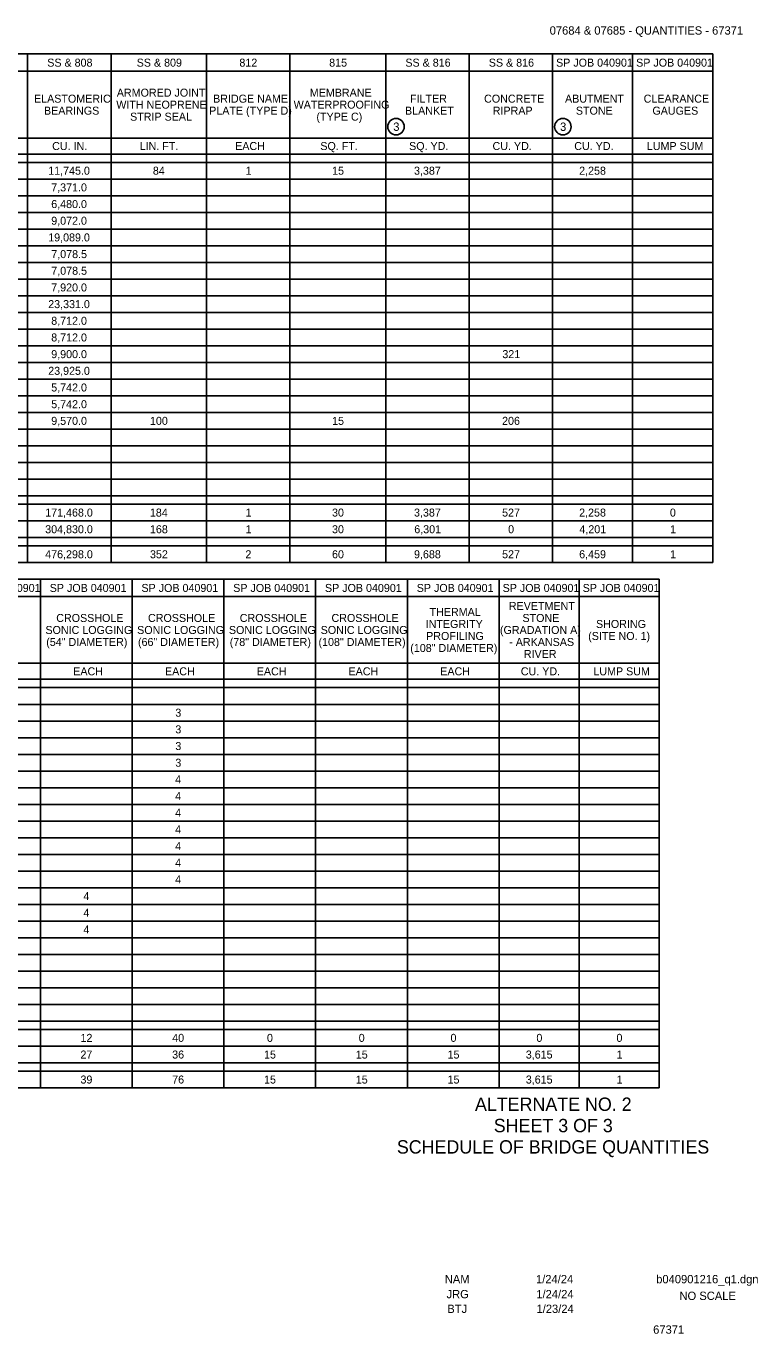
# Model space of a CAD drawing. Extents: x 0.06 to 1.36, y 0.04 to 0.85.
# Drawn here: x 0.905 to 1.362, y 0.037 to 0.854 of the extents above; entities that cross this region are included whole.
import ezdxf

# ---------------------------------------------------------------- set-up
doc = ezdxf.new("R2010")
doc.units = 0
for name, color, linetype in [('R_Shade By Others', 7, 'Continuous'), ('R_Survey Control', 7, 'Continuous'), ('R_Wall', 7, 'Continuous')]:
    doc.layers.add(name, color=color, linetype=linetype)

msp = doc.modelspace()

# ---------------------------------------------------------------- linework, layer by layer
at = {"layer": 'R_Survey Control'}
for p, q in [((0.07508, 0.83695), (1.33392, 0.83695)), ((0.90615, 0.83695), (0.90615, 0.51924)), ((0.95823, 0.83695), (0.95823, 0.51924)), ((1.0178, 0.83695), (1.0178, 0.51924)), ((1.06988, 0.83695), (1.06988, 0.51924)), ((1.12978, 0.83695), (1.12978, 0.51924)), ((1.18186, 0.83695), (1.18186, 0.51924)), ((1.23394, 0.83695), (1.23394, 0.51924)), ((1.28392, 0.83695), (1.28392, 0.51924)), ((1.33392, 0.83695), (1.33392, 0.51924)), ((0.2593, 0.78445), (1.33392, 0.78445)), ((0.07508, 0.77445), (1.33392, 0.77445)), ((0.11154, 0.76924), (1.33392, 0.76924)), ((0.11154, 0.75883), (1.33392, 0.75883)), ((0.11154, 0.74841), (1.33392, 0.74841)), ((0.11154, 0.73799), (1.33392, 0.73799)), ((0.11154, 0.72758), (1.33392, 0.72758)), ((0.11154, 0.71716), (1.33392, 0.71716)), ((0.11154, 0.70674), (1.33392, 0.70674)), ((0.11154, 0.69633), (1.33392, 0.69633)), ((0.11154, 0.68591), (1.33392, 0.68591)), ((0.11154, 0.67549), (1.33392, 0.67549)), ((0.11154, 0.66508), (1.33392, 0.66508)), ((0.11154, 0.65466), (1.33392, 0.65466)), ((0.11154, 0.64424), (1.33392, 0.64424)), ((0.11154, 0.63383), (1.33392, 0.63383)), ((0.11154, 0.62341), (1.33392, 0.62341)), ((0.11154, 0.61299), (1.33392, 0.61299)), ((0.11154, 0.60258), (1.33392, 0.60258)), ((0.11154, 0.59216), (1.33392, 0.59216)), ((0.11154, 0.58174), (1.33392, 0.58174)), ((0.11154, 0.57133), (1.33392, 0.57133)), ((0.07508, 0.5557), (1.33392, 0.5557)), ((0.11154, 0.56091), (1.33392, 0.56091)), ((0.07508, 0.54529), (1.33392, 0.54529)), ((0.07508, 0.53487), (1.33392, 0.53487)), ((0.07508, 0.52966), (1.33392, 0.52966)), ((0.07508, 0.51924), (1.33392, 0.51924)), ((0.07508, 0.50883), (1.30054, 0.50883)), ((0.9141, 0.50883), (0.9141, 0.19112)), ((0.97139, 0.50883), (0.97139, 0.19112)), ((1.02868, 0.50883), (1.02868, 0.19112)), ((1.08598, 0.50883), (1.08598, 0.19112)), ((1.14327, 0.50883), (1.14327, 0.19112)), ((1.20056, 0.50883), (1.20056, 0.19112)), ((1.25055, 0.50883), (1.25055, 0.19112)), ((1.30054, 0.50883), (1.30054, 0.19112)), ((0.2593, 0.45633), (1.30054, 0.45633)), ((0.07508, 0.44633), (1.30054, 0.44633)), ((0.11154, 0.44112), (1.30054, 0.44112)), ((0.11154, 0.4307), (1.30054, 0.4307)), ((0.11154, 0.42029), (1.30054, 0.42029)), ((0.11154, 0.40987), (1.30054, 0.40987)), ((0.11154, 0.39945), (1.30054, 0.39945)), ((0.11154, 0.38904), (1.30054, 0.38904)), ((0.11154, 0.37862), (1.30054, 0.37862)), ((0.11154, 0.3682), (1.30054, 0.3682)), ((0.11154, 0.35779), (1.30054, 0.35779)), ((0.11154, 0.34737), (1.30054, 0.34737)), ((0.11154, 0.33695), (1.30054, 0.33695)), ((0.11154, 0.32654), (1.30054, 0.32654)), ((0.11154, 0.31612), (1.30054, 0.31612)), ((0.11154, 0.3057), (1.30054, 0.3057)), ((0.11154, 0.29529), (1.30054, 0.29529)), ((0.11154, 0.28487), (1.30054, 0.28487)), ((0.11154, 0.27445), (1.30054, 0.27445)), ((0.11154, 0.26404), (1.30054, 0.26404)), ((0.11154, 0.25362), (1.30054, 0.25362)), ((0.11154, 0.2432), (1.30054, 0.2432)), ((0.11154, 0.23279), (1.30054, 0.23279)), ((0.07508, 0.22758), (1.30054, 0.22758)), ((0.07508, 0.21716), (1.30054, 0.21716)), ((0.07508, 0.20674), (1.30054, 0.20674)), ((0.07508, 0.20154), (1.30054, 0.20154)), ((0.07508, 0.19112), (1.30054, 0.19112))]:
    msp.add_line(p, q, dxfattribs=at)
for points in [[(0.2593, 0.82612), (0.30425, 0.82612), (0.41883, 0.82612), (0.46733, 0.82612), (0.509, 0.82612), (0.55587, 0.82612), (0.59233, 0.82612), (0.6366, 0.82612), (0.68087, 0.82612), (0.74858, 0.82612), (0.79433, 0.82612), (0.84642, 0.82612), (0.94537, 0.82612), (1.00267, 0.82612), (1.06517, 0.82612), (1.19277, 0.82612), (1.26048, 0.82612), (1.31256, 0.82612), (1.33392, 0.82612)], [(0.2593, 0.49799), (0.30425, 0.49799), (0.36154, 0.49799), (0.40321, 0.49799), (0.44487, 0.49799), (0.49175, 0.49799), (0.52821, 0.49799), (0.58029, 0.49799), (0.64019, 0.49799), (0.7079, 0.49799), (0.75998, 0.49799), (0.81206, 0.49799), (0.85894, 0.49799), (0.86623, 0.49799), (0.92873, 0.49799), (0.99644, 0.49799), (1.06415, 0.49799), (1.11623, 0.49799), (1.16831, 0.49799), (1.30054, 0.49799)]]:
    msp.add_lwpolyline(points, dxfattribs=at)
at = {"layer": 'R_Wall'}
for centre in [(1.13618, 0.79152), (1.24035, 0.79152)]:
    msp.add_circle(centre, 0.00515, dxfattribs=at)

# ---------------------------------------------------------------- texts
at = {"layer": 'R_Shade By Others'}
for s, height, p in [('07684 & 07685 - QUANTITIES - 67371', 0.0052083, (1.23211, 0.84904)), ('ALTERNATE NO. 2', 0.0083332, (1.18545, 0.17677)), ('SHEET 3 OF 3', 0.0083332, (1.1972, 0.16344)), ('SCHEDULE OF BRIDGE QUANTITIES', 0.0083332, (1.13669, 0.1501)), ('NAM', 0.005208, (1.1666, 0.06906)), ('1/24/24', 0.005208, (1.22357, 0.06906)), ('b040901216_q1.dgn', 0.0052083, (1.29862, 0.06906)), ('JRG', 0.005208, (1.1677, 0.05969)), ('1/24/24', 0.005208, (1.22378, 0.05969)), ('NO SCALE', 0.005208, (1.31316, 0.05864)), ('BTJ', 0.005208, (1.16819, 0.05052)), ('1/23/24', 0.005208, (1.22389, 0.05052)), ('67371', 0.005208, (1.29672, 0.03756))]:
    msp.add_text(s, height=height, dxfattribs=at).set_placement(p)
at = {"layer": 'R_Survey Control'}
for s, p in [('SS & 808', (0.91839, 0.82904)), ('SS & 809', (0.97424, 0.82904)), ('812', (1.03836, 0.82904)), ('815', (1.09443, 0.82904)), ('SS & 816', (1.14201, 0.82904)), ('SS & 816', (1.19409, 0.82904)), ('SP JOB 040901', (1.2361, 0.82904)), ('SP JOB 040901', (1.2861, 0.82904)), ('ELASTOMERIC', (0.91013, 0.80654)), ('ARMORED JOINT', (0.96182, 0.81029)), ('BRIDGE NAME', (1.02194, 0.80654)), ('MEMBRANE', (1.08232, 0.81029)), ('FILTER', (1.14491, 0.80654)), ('CONCRETE', (1.19116, 0.80654)), ('ABUTMENT', (1.24169, 0.80654)), ('CLEARANCE', (1.29079, 0.80654)), ('BEARINGS', (0.91634, 0.79904)), ('WITH NEOPRENE', (0.9615, 0.80279)), ('PLATE (TYPE D)', (1.01949, 0.79904)), ('WATERPROOFING', (1.07225, 0.80279)), ('(TYPE C)', (1.08648, 0.79529)), ('BLANKET', (1.14177, 0.79904)), ('RIPRAP', (1.19656, 0.79904)), ('STONE', (1.24846, 0.79904)), ('GAUGES', (1.29626, 0.79904)), ('STRIP SEAL', (0.9701, 0.79529)), ('CU. IN.', (0.92146, 0.77695)), ('LIN. FT.', (0.97609, 0.77695)), ('EACH', (1.03572, 0.77695)), ('SQ. FT.', (1.0889, 0.77695)), ('SQ. YD.', (1.14432, 0.77695)), ('CU. YD.', (1.19643, 0.77695)), ('CU. YD.', (1.24746, 0.77695)), ('LUMP SUM', (1.29277, 0.77695)), ('11,745.0', (0.91899, 0.76154)), ('84', (0.98435, 0.76154)), ('1', (1.04224, 0.76154)), ('15', (1.09625, 0.76154)), ('3,387', (1.1474, 0.76154)), ('2,258', (1.25051, 0.76154)), ('7,371.0', (0.92087, 0.75112)), ('6,480.0', (0.92087, 0.7407)), ('9,072.0', (0.92087, 0.73029)), ('19,089.0', (0.91899, 0.71987)), ('7,078.5', (0.92091, 0.70945)), ('7,078.5', (0.92091, 0.69904)), ('7,920.0', (0.92087, 0.68862)), ('23,331.0', (0.91899, 0.6782)), ('8,712.0', (0.92087, 0.66779)), ('8,712.0', (0.92087, 0.65737)), ('9,900.0', (0.92087, 0.64695)), ('321', (1.20255, 0.64695)), ('23,925.0', (0.91899, 0.63654)), ('5,742.0', (0.92087, 0.62612)), ('5,742.0', (0.92087, 0.6157)), ('9,570.0', (0.92087, 0.60529)), ('100', (0.98253, 0.60529)), ('15', (1.09625, 0.60529)), ('206', (1.20239, 0.60529)), ('171,468.0', (0.91711, 0.54799)), ('184', (0.98247, 0.54799)), ('1', (1.04224, 0.54799)), ('30', (1.09621, 0.54799)), ('3,387', (1.1474, 0.54799)), ('527', (1.2024, 0.54799)), ('2,258', (1.25051, 0.54799)), ('0', (1.30718, 0.54799)), ('304,830.0', (0.91711, 0.53758)), ('168', (0.98251, 0.53758)), ('1', (1.04224, 0.53758)), ('30', (1.09621, 0.53758)), ('6,301', (1.14755, 0.53758)), ('0', (1.20616, 0.53758)), ('4,201', (1.25066, 0.53758)), ('1', (1.30732, 0.53758)), ('476,298.0', (0.91711, 0.52195)), ('352', (0.98254, 0.52195)), ('2', (1.04212, 0.52195)), ('60', (1.09621, 0.52195)), ('9,688', (1.1474, 0.52195)), ('527', (1.2024, 0.52195)), ('6,459', (1.25053, 0.52195)), ('1', (1.30732, 0.52195)), ('SP JOB 040901', (0.86628, 0.50091)), ('SP JOB 040901', (0.91992, 0.50091)), ('SP JOB 040901', (0.97721, 0.50091)), ('SP JOB 040901', (1.0345, 0.50091)), ('SP JOB 040901', (1.09179, 0.50091)), ('SP JOB 040901', (1.14909, 0.50091)), ('SP JOB 040901', (1.20273, 0.50091)), ('SP JOB 040901', (1.25271, 0.50091)), ('THERMAL', (1.15711, 0.48591)), ('REVETMENT', (1.20662, 0.48966)), ('CROSSHOLE', (0.92401, 0.48216)), ('CROSSHOLE', (0.9813, 0.48216)), ('CROSSHOLE', (1.03859, 0.48216)), ('CROSSHOLE', (1.09588, 0.48216)), ('INTEGRITY', (1.15468, 0.47841)), ('STONE', (1.21509, 0.48216)), ('SHORING', (1.26103, 0.47841)), ('SONIC LOGGING', (0.91724, 0.47466)), ('SONIC LOGGING', (0.97453, 0.47466)), ('SONIC LOGGING', (1.03182, 0.47466)), ('SONIC LOGGING', (1.08912, 0.47466)), ('PROFILING', (1.15496, 0.47091)), ('(GRADATION A)', (1.20106, 0.47466)), ('(SITE NO. 1)', (1.25616, 0.47091)), ('(54" DIAMETER)', (0.91776, 0.46716)), ('(66" DIAMETER)', (0.97505, 0.46716)), ('(78" DIAMETER)', (1.03235, 0.46716)), ('(108" DIAMETER)', (1.08776, 0.46716)), ('(108" DIAMETER)', (1.14505, 0.46341)), ('- ARKANSAS', (1.20685, 0.46716)), ('RIVER', (1.21597, 0.45966)), ('EACH', (0.93462, 0.44883)), ('EACH', (0.99191, 0.44883)), ('EACH', (1.04921, 0.44883)), ('EACH', (1.1065, 0.44883)), ('EACH', (1.16379, 0.44883)), ('CU. YD.', (1.21409, 0.44883)), ('LUMP SUM', (1.25939, 0.44883)), ('3', (0.99836, 0.42299)), ('3', (0.99836, 0.41258)), ('3', (0.99836, 0.40216)), ('3', (0.99836, 0.39174)), ('4', (0.99825, 0.38133)), ('4', (0.99825, 0.37091)), ('4', (0.99825, 0.36049)), ('4', (0.99825, 0.35008)), ('4', (0.99825, 0.33966)), ('4', (0.99825, 0.32924)), ('4', (0.99825, 0.31883)), ('4', (0.94096, 0.30841)), ('4', (0.94096, 0.29799)), ('4', (0.94096, 0.28758)), ('12', (0.93915, 0.21987)), ('40', (0.99642, 0.21987)), ('0', (1.05559, 0.21987)), ('0', (1.11288, 0.21987)), ('0', (1.17018, 0.21987)), ('0', (1.22382, 0.21987)), ('0', (1.2738, 0.21987)), ('27', (0.93912, 0.20945)), ('36', (0.9964, 0.20945)), ('15', (1.05376, 0.20945)), ('15', (1.11105, 0.20945)), ('15', (1.16834, 0.20945)), ('3,615', (1.21719, 0.20945)), ('1', (1.27394, 0.20945)), ('39', (0.93914, 0.19383)), ('76', (0.9964, 0.19383)), ('15', (1.05376, 0.19383)), ('15', (1.11105, 0.19383)), ('15', (1.16834, 0.19383)), ('3,615', (1.21719, 0.19383)), ('1', (1.27394, 0.19383))]:
    msp.add_text(s, height=0.005, dxfattribs=at).set_placement(p)
at = {"layer": 'R_Wall'}
for p in [(1.13443, 0.78892), (1.2386, 0.78892)]:
    msp.add_text('3', height=0.00521, dxfattribs=at).set_placement(p)

doc.saveas('drawing.dxf')
